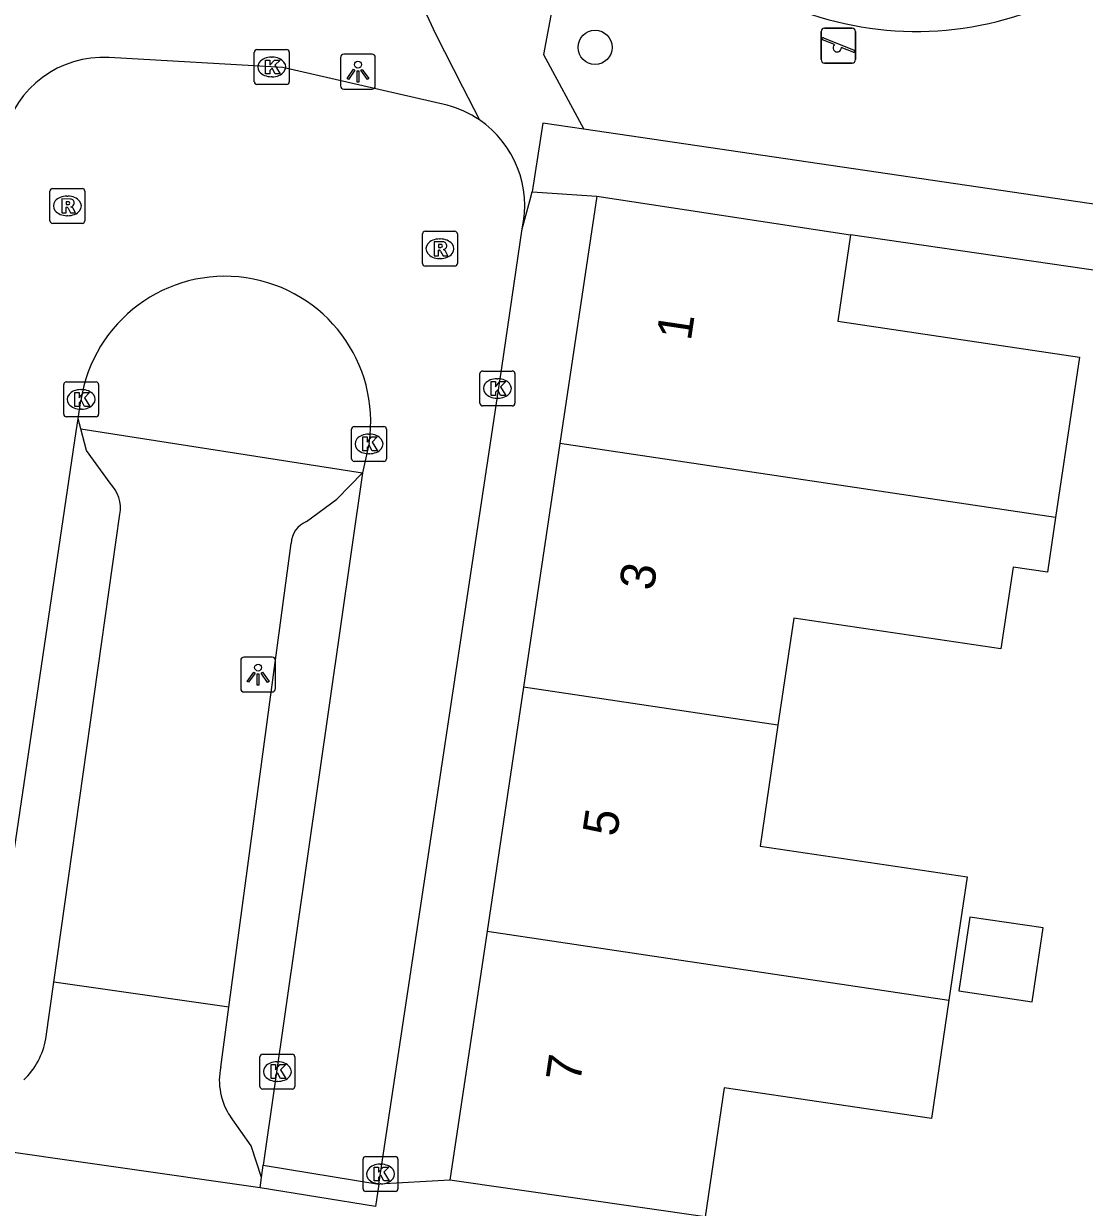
# Model space of a CAD drawing. Extents: x 163686 to 164493, y 382719 to 383870.
# Drawn here: x 164044.41 to 164074.82, y 383054.57 to 383088.49 of the extents above; entities that cross this region are included whole.
import ezdxf

# ---------------------------------------------------------------- set-up
doc = ezdxf.new("R2010")
doc.units = 0
for name, color, linetype in [('IMGEO_Boom', 7, 'Continuous'), ('IMGEO_Groenvoorziening', 7, 'Continuous'), ('IMGEO_Kolk', 7, 'Continuous'), ('IMGEO_Lichtpunt', 7, 'Continuous'), ('IMGEO_Pand', 7, 'Continuous'), ('IMGEO_Pand_nummerreeks', 7, 'Continuous'), ('IMGEO_Parkeervlak_open', 7, 'Continuous'), ('IMGEO_Rijbaan_lokaal_open', 7, 'Continuous'), ('IMGEO_Rioolput', 7, 'Continuous'), ('IMGEO_Speelvoorziening', 7, 'Continuous'), ('IMGEO_Voetpad_halfverhard', 7, 'Continuous'), ('IMGEO_Voetpad_open', 7, 'Continuous')]:
    doc.layers.add(name, color=color, linetype=linetype)

msp = doc.modelspace()

# ---------------------------------------------------------------- linework, layer by layer
at = {"layer": 'IMGEO_Boom'}
msp.add_circle((164060.792, 383087.809), 0.489, dxfattribs=at)
at = {"layer": 'IMGEO_Groenvoorziening'}
for points in [[(164046.049, 383076.883), (164054.125, 383075.618)], [(164050.291, 383060.313), (164045.275, 383061.028)]]:
    msp.add_lwpolyline(points, dxfattribs=at)
msp.add_arc((164070.002, 383097.777), 9.511, 241.1391, 288.5724, dxfattribs=at)
at = {"layer": 'IMGEO_Kolk'}
for p, q in [((164051.024, 383086.821), (164051.024, 383087.673)), ((164051.099, 383087.747), (164051.951, 383087.747)), ((164052.025, 383087.673), (164052.025, 383086.821)), ((164051.512, 383087.527), (164051.537, 383087.527)), ((164051.951, 383086.747), (164051.099, 383086.747)), ((164051.535, 383086.967), (164051.51, 383086.967)), ((164057.567, 383078.536), (164058.419, 383078.536)), ((164045.635, 383078.223), (164046.487, 383078.223)), ((164057.492, 383077.61), (164057.492, 383078.462)), ((164057.98, 383078.316), (164058.005, 383078.316)), ((164058.493, 383078.462), (164058.493, 383077.61)), ((164045.56, 383077.297), (164045.56, 383078.149)), ((164046.048, 383078.003), (164046.073, 383078.003)), ((164046.561, 383078.149), (164046.561, 383077.297)), ((164058.419, 383077.536), (164057.567, 383077.536)), ((164058.003, 383077.756), (164057.978, 383077.756)), ((164046.487, 383077.223), (164045.635, 383077.223)), ((164046.071, 383077.443), (164046.046, 383077.443)), ((164053.812, 383076.021), (164053.812, 383076.873)), ((164053.887, 383076.947), (164054.739, 383076.947)), ((164054.813, 383076.873), (164054.813, 383076.021)), ((164054.3, 383076.727), (164054.325, 383076.727)), ((164054.323, 383076.167), (164054.298, 383076.167)), ((164054.739, 383075.947), (164053.887, 383075.947)), ((164051.185, 383058.036), (164051.185, 383058.888)), ((164051.26, 383058.962), (164052.112, 383058.962)), ((164052.186, 383058.888), (164052.186, 383058.036)), ((164051.673, 383058.742), (164051.698, 383058.742)), ((164051.696, 383058.182), (164051.671, 383058.182)), ((164052.112, 383057.962), (164051.26, 383057.962)), ((164054.141, 383055.103), (164054.141, 383055.955)), ((164054.216, 383056.029), (164055.068, 383056.029)), ((164054.629, 383055.809), (164054.654, 383055.809)), ((164055.142, 383055.955), (164055.142, 383055.103)), ((164054.652, 383055.249), (164054.627, 383055.249)), ((164055.068, 383055.029), (164054.216, 383055.029))]:
    msp.add_line(p, q, dxfattribs=at)
for points in [[(164051.024, 383086.821), (164051.024, 383087.673)], [(164051.099, 383087.747), (164051.951, 383087.747)], [(164052.025, 383087.673), (164052.025, 383086.821)], [(164051.345, 383087.447), (164051.468, 383087.447), (164051.468, 383087.296), (164051.598, 383087.447), (164051.762, 383087.447), (164051.616, 383087.296), (164051.769, 383087.047), (164051.617, 383087.047), (164051.532, 383087.211), (164051.468, 383087.144), (164051.468, 383087.047), (164051.345, 383087.047), (164051.345, 383087.447)], [(164051.951, 383086.747), (164051.099, 383086.747)], [(164057.567, 383078.536), (164058.419, 383078.536)], [(164045.635, 383078.223), (164046.487, 383078.223)], [(164057.492, 383077.61), (164057.492, 383078.462)], [(164057.813, 383078.236), (164057.936, 383078.236), (164057.936, 383078.085), (164058.066, 383078.236), (164058.23, 383078.236), (164058.084, 383078.085), (164058.237, 383077.836), (164058.085, 383077.836), (164058, 383078), (164057.936, 383077.933), (164057.936, 383077.836), (164057.813, 383077.836), (164057.813, 383078.236)], [(164058.493, 383078.462), (164058.493, 383077.61)], [(164045.56, 383077.297), (164045.56, 383078.149)], [(164045.881, 383077.923), (164046.004, 383077.923), (164046.004, 383077.772), (164046.134, 383077.923), (164046.298, 383077.923), (164046.152, 383077.772), (164046.305, 383077.523), (164046.153, 383077.523), (164046.068, 383077.687), (164046.004, 383077.62), (164046.004, 383077.523), (164045.881, 383077.523), (164045.881, 383077.923)], [(164046.561, 383078.149), (164046.561, 383077.297)], [(164058.419, 383077.536), (164057.567, 383077.536)], [(164046.487, 383077.223), (164045.635, 383077.223)], [(164053.812, 383076.021), (164053.812, 383076.873)], [(164053.887, 383076.947), (164054.739, 383076.947)], [(164054.813, 383076.873), (164054.813, 383076.021)], [(164054.133, 383076.647), (164054.256, 383076.647), (164054.256, 383076.496), (164054.386, 383076.647), (164054.55, 383076.647), (164054.404, 383076.496), (164054.557, 383076.247), (164054.405, 383076.247), (164054.32, 383076.411), (164054.256, 383076.344), (164054.256, 383076.247), (164054.133, 383076.247), (164054.133, 383076.647)], [(164054.739, 383075.947), (164053.887, 383075.947)], [(164051.185, 383058.036), (164051.185, 383058.888)], [(164051.26, 383058.962), (164052.112, 383058.962)], [(164052.186, 383058.888), (164052.186, 383058.036)], [(164051.506, 383058.662), (164051.629, 383058.662), (164051.629, 383058.511), (164051.759, 383058.662), (164051.923, 383058.662), (164051.777, 383058.511), (164051.93, 383058.262), (164051.778, 383058.262), (164051.693, 383058.426), (164051.629, 383058.359), (164051.629, 383058.262), (164051.506, 383058.262), (164051.506, 383058.662)], [(164052.112, 383057.962), (164051.26, 383057.962)], [(164054.141, 383055.103), (164054.141, 383055.955)], [(164054.216, 383056.029), (164055.068, 383056.029)], [(164055.142, 383055.955), (164055.142, 383055.103)], [(164054.462, 383055.729), (164054.585, 383055.729), (164054.585, 383055.578), (164054.715, 383055.729), (164054.879, 383055.729), (164054.733, 383055.578), (164054.886, 383055.329), (164054.734, 383055.329), (164054.649, 383055.493), (164054.585, 383055.426), (164054.585, 383055.329), (164054.462, 383055.329), (164054.462, 383055.729)], [(164055.068, 383055.029), (164054.216, 383055.029)]]:
    msp.add_lwpolyline(points, dxfattribs=at)
for centre, start, end in [((164051.101, 383087.671), 91.552, 178.448), ((164051.101, 383087.671), 91.552, 178.448), ((164051.949, 383087.671), 1.552, 88.448), ((164051.949, 383087.671), 1.552, 88.448), ((164051.101, 383086.823), 181.552, 268.448), ((164051.101, 383086.823), 181.552, 268.448), ((164051.949, 383086.823), 271.552, 358.448), ((164051.949, 383086.823), 271.552, 358.448), ((164057.569, 383078.46), 91.552, 178.448), ((164057.569, 383078.46), 91.552, 178.448), ((164058.417, 383078.46), 1.552, 88.448), ((164058.417, 383078.46), 1.552, 88.448), ((164045.637, 383078.147), 91.552, 178.448), ((164045.637, 383078.147), 91.552, 178.448), ((164046.485, 383078.147), 1.552, 88.448), ((164046.485, 383078.147), 1.552, 88.448), ((164057.569, 383077.612), 181.552, 268.448), ((164057.569, 383077.612), 181.552, 268.448), ((164058.417, 383077.612), 271.552, 358.448), ((164058.417, 383077.612), 271.552, 358.448), ((164045.637, 383077.299), 181.552, 268.448), ((164045.637, 383077.299), 181.552, 268.448), ((164046.485, 383077.299), 271.552, 358.448), ((164046.485, 383077.299), 271.552, 358.448), ((164053.889, 383076.871), 91.552, 178.448), ((164053.889, 383076.871), 91.552, 178.448), ((164054.737, 383076.871), 1.552, 88.448), ((164054.737, 383076.871), 1.552, 88.448), ((164053.889, 383076.023), 181.552, 268.448), ((164053.889, 383076.023), 181.552, 268.448), ((164054.737, 383076.023), 271.552, 358.448), ((164054.737, 383076.023), 271.552, 358.448), ((164051.262, 383058.886), 91.552, 178.448), ((164051.262, 383058.886), 91.552, 178.448), ((164052.11, 383058.886), 1.552, 88.448), ((164052.11, 383058.886), 1.552, 88.448), ((164051.262, 383058.038), 181.552, 268.448), ((164051.262, 383058.038), 181.552, 268.448), ((164052.11, 383058.038), 271.552, 358.448), ((164052.11, 383058.038), 271.552, 358.448), ((164054.218, 383055.953), 91.552, 178.448), ((164054.218, 383055.953), 91.552, 178.448), ((164055.066, 383055.953), 1.552, 88.448), ((164055.066, 383055.953), 1.552, 88.448), ((164054.218, 383055.105), 181.552, 268.448), ((164054.218, 383055.105), 181.552, 268.448), ((164055.066, 383055.105), 271.552, 358.448), ((164055.066, 383055.105), 271.552, 358.448)]:
    msp.add_arc(centre, 0.0765, start, end, dxfattribs=at)
for centre, major_axis, ratio, start_param, end_param in [((164051.511, 383087.247), (-0.387, 0.002), 0.722429, 4.712389, 7.853982), ((164051.536, 383087.247), (-0.39, 0.002), 0.717154, 1.570796, 4.712389), ((164057.979, 383078.036), (-0.387, 0.002), 0.722429, 4.712389, 7.853982), ((164058.004, 383078.036), (-0.39, 0.002), 0.717154, 1.570796, 4.712389), ((164046.047, 383077.723), (-0.387, 0.002), 0.722429, 4.712389, 7.853982), ((164046.072, 383077.723), (-0.39, 0.002), 0.717154, 1.570796, 4.712389), ((164054.299, 383076.447), (-0.387, 0.002), 0.722429, 4.712389, 7.853982), ((164054.324, 383076.447), (-0.39, 0.002), 0.717154, 1.570796, 4.712389), ((164051.672, 383058.462), (-0.387, 0.002), 0.722429, 4.712389, 7.853982), ((164051.697, 383058.462), (-0.39, 0.002), 0.717154, 1.570796, 4.712389), ((164054.628, 383055.529), (-0.387, 0.002), 0.722429, 4.712389, 7.853982), ((164054.653, 383055.529), (-0.39, 0.002), 0.717154, 1.570796, 4.712389)]:
    msp.add_ellipse(centre, major_axis=major_axis, ratio=ratio, start_param=start_param, end_param=end_param, dxfattribs=at)
at = {"layer": 'IMGEO_Lichtpunt'}
for p, q in [((164053.496, 383087.516), (164053.496, 383086.709)), ((164053.496, 383087.516), (164053.496, 383086.709)), ((164054.398, 383087.611), (164053.59, 383087.611)), ((164054.398, 383087.611), (164053.59, 383087.611)), ((164054.492, 383086.709), (164054.492, 383087.516)), ((164054.492, 383086.709), (164054.492, 383087.516)), ((164053.59, 383086.615), (164054.398, 383086.615)), ((164053.59, 383086.615), (164054.398, 383086.615)), ((164050.634, 383070.242), (164050.634, 383069.435)), ((164050.634, 383070.242), (164050.634, 383069.435)), ((164051.536, 383070.337), (164050.728, 383070.337)), ((164051.536, 383070.337), (164050.728, 383070.337)), ((164051.63, 383069.435), (164051.63, 383070.242)), ((164051.63, 383069.435), (164051.63, 383070.242)), ((164050.728, 383069.341), (164051.536, 383069.341)), ((164050.728, 383069.341), (164051.536, 383069.341))]:
    msp.add_line(p, q, dxfattribs=at)
for points in [[(164053.87, 383087.18), (164053.909, 383087.152), (164053.721, 383086.89), (164053.683, 383086.917), (164053.87, 383087.18)], [(164053.972, 383087.132), (164054.019, 383087.132), (164054.019, 383086.81), (164053.972, 383086.81), (164053.972, 383087.132)], [(164054.082, 383087.152), (164054.12, 383087.179), (164054.307, 383086.917), (164054.268, 383086.889), (164054.082, 383087.152)], [(164051.008, 383069.906), (164051.047, 383069.878), (164050.859, 383069.616), (164050.821, 383069.643), (164051.008, 383069.906)], [(164051.11, 383069.858), (164051.157, 383069.858), (164051.157, 383069.536), (164051.11, 383069.536), (164051.11, 383069.858)], [(164051.22, 383069.878), (164051.258, 383069.905), (164051.445, 383069.643), (164051.406, 383069.615), (164051.22, 383069.878)]]:
    msp.add_lwpolyline(points, dxfattribs=at)
for centre in [(164053.995, 383087.314), (164051.133, 383070.04)]:
    msp.add_circle(centre, 0.0994, dxfattribs=at)
for centre, start, end in [((164053.59, 383087.516), 90, 180), ((164053.59, 383087.516), 90, 180), ((164054.398, 383087.516), 0, 90), ((164054.398, 383087.516), 0, 90), ((164053.59, 383086.709), 180, 270), ((164053.59, 383086.709), 180, 270), ((164054.398, 383086.709), 270, 0), ((164054.398, 383086.709), 270, 360), ((164050.728, 383070.242), 90, 180), ((164050.728, 383070.242), 90, 180), ((164051.536, 383070.242), 0, 90), ((164051.536, 383070.242), 0, 90), ((164050.728, 383069.435), 180, 270), ((164050.728, 383069.435), 180, 270), ((164051.536, 383069.435), 270, 0), ((164051.536, 383069.435), 270, 360)]:
    msp.add_arc(centre, 0.0946, start, end, dxfattribs=at)
at = {"layer": 'IMGEO_Pand'}
for points in [[(164060.842, 383083.547), (164059.784, 383076.46)], [(164060.842, 383083.547), (164068.118, 383082.441)], [(164068.118, 383082.441), (164067.751, 383079.962), (164074.676, 383078.936), (164074.495, 383077.716), (164073.995, 383074.34)], [(164059.784, 383076.46), (164058.741, 383069.474)], [(164073.995, 383074.34), (164059.784, 383076.46)], [(164073.995, 383074.34), (164073.762, 383072.77), (164072.773, 383072.917), (164072.426, 383070.573), (164066.489, 383071.452), (164066.035, 383068.386)], [(164058.741, 383069.474), (164057.698, 383062.488)], [(164066.035, 383068.386), (164058.741, 383069.474)], [(164066.035, 383068.386), (164065.522, 383064.923), (164071.458, 383064.044), (164071.165, 383062.066), (164070.935, 383060.513)], [(164073.633, 383062.582), (164071.536, 383062.892), (164071.222, 383060.775), (164073.319, 383060.464), (164073.633, 383062.582)], [(164057.698, 383062.488), (164056.633, 383055.356)], [(164057.698, 383062.488), (164070.935, 383060.513)], [(164070.935, 383060.513), (164070.432, 383057.12), (164064.496, 383057.999), (164063.947, 383054.299)], [(164063.947, 383054.299), (164056.633, 383055.356)]]:
    msp.add_lwpolyline(points, dxfattribs=at)
at = {"layer": 'IMGEO_Parkeervlak_open'}
for points in [[(164046.049, 383076.883), (164045.976, 383077.163)], [(164046.887, 383075.323), (164046.212, 383076.262), (164046.049, 383076.883)], [(164052.524, 383074.226), (164053.388, 383074.861), (164054.125, 383075.618)], [(164045.275, 383061.028), (164047.17, 383074.431)], [(164050.291, 383060.313), (164052.079, 383073.592)], [(164045.045, 383059.399), (164045.275, 383061.028)], [(164050.06, 383058.594), (164050.291, 383060.313)], [(164051.231, 383055.427), (164050.934, 383056.333), (164050.338, 383057.172)]]:
    msp.add_lwpolyline(points, dxfattribs=at)
for centre, radius, start, end in [((164046.184, 383074.609), 1.002, 349.7759, 45.4289), ((164052.784, 383073.57), 0.705, 111.6311, 178.2395), ((164042.941, 383059.772), 2.137, 313.5087, 349.9478), ((164051.895, 383058.215), 1.874, 168.3167, 213.8069)]:
    msp.add_arc(centre, radius, start, end, dxfattribs=at)
at = {"layer": 'IMGEO_Rijbaan_lokaal_open'}
for points in [[(164056.551, 383086.15), (164051.838, 383087.231), (164046.861, 383087.515)], [(164054.596, 383055.242), (164058.121, 383078.624), (164058.702, 383082.608)], [(164045.976, 383077.163), (164046.054, 383077.691)], [(164042.978, 383056.96), (164045.921, 383076.806), (164045.976, 383077.163)], [(164054.32, 383076.482), (164054.125, 383075.618)], [(164054.125, 383075.618), (164051.281, 383055.779)], [(164051.231, 383055.427), (164051.281, 383055.779)], [(164051.281, 383055.779), (164054.596, 383055.242)], [(164051.188, 383055.135), (164051.231, 383055.427)], [(164054.596, 383055.242), (164054.5, 383054.599), (164051.188, 383055.135)]]:
    msp.add_lwpolyline(points, dxfattribs=at)
for centre, radius, start, end in [((164046.687, 383084.602), 2.919, 86.5909, 166.3776), ((164055.814, 383083.291), 2.953, 55.771, 75.5468), ((164055.805, 383083.273), 2.972, 347.0708, 55.8156), ((164050.185, 383077.072), 4.177, 351.8809, 171.4767)]:
    msp.add_arc(centre, radius, start, end, dxfattribs=at)
at = {"layer": 'IMGEO_Rioolput'}
for p, q in [((164045.165, 383082.84), (164045.165, 383083.692)), ((164045.24, 383083.766), (164046.092, 383083.766)), ((164046.166, 383083.692), (164046.166, 383082.84)), ((164045.653, 383083.546), (164045.678, 383083.546)), ((164045.676, 383082.986), (164045.651, 383082.986)), ((164046.092, 383082.766), (164045.24, 383082.766)), ((164055.843, 383081.614), (164055.843, 383082.466)), ((164055.918, 383082.54), (164056.77, 383082.54)), ((164056.331, 383082.32), (164056.356, 383082.32)), ((164056.844, 383082.466), (164056.844, 383081.614)), ((164056.354, 383081.76), (164056.329, 383081.76)), ((164056.77, 383081.54), (164055.918, 383081.54))]:
    msp.add_line(p, q, dxfattribs=at)
for points in [[(164045.165, 383082.84), (164045.165, 383083.692)], [(164045.24, 383083.766), (164046.092, 383083.766)], [(164046.166, 383083.692), (164046.166, 383082.84)], [(164045.754, 383083.464), (164045.502, 383083.466), (164045.502, 383083.066)], [(164045.68, 383083.385), (164045.626, 383083.385), (164045.626, 383083.304)], [(164045.626, 383083.304), (164045.678, 383083.304)], [(164045.502, 383083.066), (164045.626, 383083.066), (164045.626, 383083.228), (164045.637, 383083.228)], [(164045.684, 383083.199), (164045.755, 383083.066), (164045.895, 383083.066), (164045.83, 383083.192)], [(164046.092, 383082.766), (164045.24, 383082.766)], [(164055.843, 383081.614), (164055.843, 383082.466)], [(164055.918, 383082.54), (164056.77, 383082.54)], [(164056.432, 383082.238), (164056.18, 383082.24), (164056.18, 383081.84)], [(164056.844, 383082.466), (164056.844, 383081.614)], [(164056.18, 383081.84), (164056.304, 383081.84), (164056.304, 383082.002), (164056.315, 383082.002)], [(164056.358, 383082.159), (164056.304, 383082.159), (164056.304, 383082.078)], [(164056.304, 383082.078), (164056.356, 383082.078)], [(164056.362, 383081.973), (164056.433, 383081.84), (164056.573, 383081.84), (164056.508, 383081.966)], [(164056.77, 383081.54), (164055.918, 383081.54)]]:
    msp.add_lwpolyline(points, dxfattribs=at)
for centre, radius, start, end in [((164045.242, 383083.69), 0.0765, 91.552, 178.448), ((164045.242, 383083.69), 0.0765, 91.552, 178.448), ((164046.09, 383083.69), 0.0765, 1.552, 88.448), ((164046.09, 383083.69), 0.0765, 1.552, 88.448), ((164045.662, 383083.493), 0.19, 274.7715, 282.9687), ((164045.686, 383083.289), 0.0964, 77.0061, 93.1865), ((164045.7, 383083.346), 0.0378, 276.6634, 79.6772), ((164045.753, 383083.354), 0.109, 350.3612, 89.416), ((164045.751, 383083.354), 0.112, 277.5842, 350.9817), ((164045.735, 383083.139), 0.108, 29.5134, 73.7905), ((164045.636, 383083.175), 0.0533, 26.0293, 88.6989), ((164045.242, 383082.842), 0.0765, 181.552, 268.448), ((164045.242, 383082.842), 0.0765, 181.552, 268.448), ((164046.09, 383082.842), 0.0765, 271.552, 358.448), ((164046.09, 383082.842), 0.0765, 271.552, 358.448), ((164055.92, 383082.464), 0.0765, 91.552, 178.448), ((164055.92, 383082.464), 0.0765, 91.552, 178.448), ((164056.431, 383082.128), 0.109, 350.3612, 89.416), ((164056.768, 383082.464), 0.0765, 1.552, 88.448), ((164056.768, 383082.464), 0.0765, 1.552, 88.448), ((164056.314, 383081.949), 0.0533, 26.0293, 88.6989), ((164056.34, 383082.267), 0.19, 274.7715, 282.9687), ((164056.364, 383082.063), 0.0964, 77.0061, 93.1865), ((164056.378, 383082.12), 0.0378, 276.6634, 79.6772), ((164056.429, 383082.128), 0.112, 277.5842, 350.9817), ((164056.413, 383081.913), 0.108, 29.5134, 73.7905), ((164055.92, 383081.616), 0.0765, 181.552, 268.448), ((164055.92, 383081.616), 0.0765, 181.552, 268.448), ((164056.768, 383081.616), 0.0765, 271.552, 358.448), ((164056.768, 383081.616), 0.0765, 271.552, 358.448)]:
    msp.add_arc(centre, radius, start, end, dxfattribs=at)
for centre, major_axis, ratio, start_param, end_param in [((164045.652, 383083.266), (-0.387, 0.002), 0.722429, 4.712389, 7.853982), ((164045.677, 383083.266), (-0.39, 0.002), 0.717154, 1.570796, 4.712389), ((164056.33, 383082.04), (-0.387, 0.002), 0.722429, 4.712389, 7.853982), ((164056.355, 383082.04), (-0.39, 0.002), 0.717154, 1.570796, 4.712389)]:
    msp.add_ellipse(centre, major_axis=major_axis, ratio=ratio, start_param=start_param, end_param=end_param, dxfattribs=at)
at = {"layer": 'IMGEO_Speelvoorziening'}
for p, q in [((164067.37, 383088.359), (164068.16, 383088.359)), ((164068.16, 383088.359), (164067.37, 383088.359)), ((164067.27, 383087.459), (164067.27, 383088.259)), ((164067.27, 383088.259), (164067.27, 383087.459)), ((164067.653, 383087.887), (164067.314, 383088.024)), ((164067.339, 383088.084), (164068.215, 383087.731)), ((164068.26, 383088.259), (164068.26, 383087.459)), ((164068.26, 383087.459), (164068.26, 383088.259)), ((164068.191, 383087.671), (164067.851, 383087.808)), ((164068.16, 383087.359), (164067.37, 383087.359)), ((164067.37, 383087.359), (164068.16, 383087.359))]:
    msp.add_line(p, q, dxfattribs=at)
for centre, radius, start, end in [((164067.37, 383088.259), 0.1, 90, 180), ((164067.37, 383088.259), 0.1, 90, 180), ((164068.16, 383088.259), 0.1, 0, 90), ((164068.16, 383088.259), 0.1, 360, 90), ((164067.327, 383088.054), 0.0327, 68.078, 248.078), ((164067.732, 383087.797), 0.12, 130.9928, 5.1632), ((164068.203, 383087.701), 0.0327, 248.078, 68.078), ((164067.37, 383087.459), 0.1, 180, 270), ((164067.37, 383087.459), 0.1, 180, 270), ((164068.16, 383087.459), 0.1, 270, 0), ((164068.16, 383087.459), 0.1, 270, 0)]:
    msp.add_arc(centre, radius, start, end, dxfattribs=at)
at = {"layer": 'IMGEO_Voetpad_halfverhard'}
for points in [[(164063.914, 383096.136), (164060.271, 383092.698), (164059.314, 383087.6), (164060.473, 383085.465)], [(164054.802, 383091.242), (164056.22, 383088.197), (164056.991, 383086.679), (164057.475, 383085.732)]]:
    msp.add_lwpolyline(points, dxfattribs=at)
at = {"layer": 'IMGEO_Voetpad_open'}
for points in [[(164060.473, 383085.465), (164059.298, 383085.638), (164058.992, 383083.665)], [(164077.551, 383082.956), (164060.473, 383085.465)], [(164058.702, 383082.608), (164058.72, 383082.673), (164058.921, 383083.408), (164058.992, 383083.665)], [(164058.992, 383083.665), (164060.842, 383083.547)], [(164079.081, 383080.842), (164068.118, 383082.441)], [(164051.188, 383055.135), (164042.84, 383056.324)], [(164056.633, 383055.356), (164054.596, 383055.242)]]:
    msp.add_lwpolyline(points, dxfattribs=at)

# ---------------------------------------------------------------- texts
at = {"layer": 'IMGEO_Pand_nummerreeks'}
for s, rotation, p in [('1', 81.509, (164063.536, 383079.379)), ('3', 81.5083, (164062.467, 383072.218)), ('5', 81.5083, (164061.415, 383065.17)), ('7', 81.5083, (164060.362, 383058.123))]:
    msp.add_text(s, height=1, rotation=rotation, dxfattribs=at).set_placement(p)

doc.saveas('drawing.dxf')
